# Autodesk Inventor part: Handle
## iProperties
Author: Elise Moss
Created: 2001-09
Part Number: Handle
Document SubType Name: Modeling
Designer: Elise Moss
Control State: 0
Master: False
Checked Out: False
PropertySet Name: Design Tracking Control
Length Units: 11272
Angle Units: 11279
Time Units: 11290
Mass Units: 11286
Shininess: 3
Angle Display Precision: 2
Document Length Units: 11272
Document Angle Units: 11286
Document Time Units: 11279
Document Mass Units: 11290
Document Length Units Precision: 3
Document Angle Units Precision: 0
Compacted: False
PropertySet Name: _Private Model Information
Density: 0.0
Volumn: 0.0
Area: 0.0
PropertySet Name: Model Information
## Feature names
1. Revolution1
2. Fillet1
